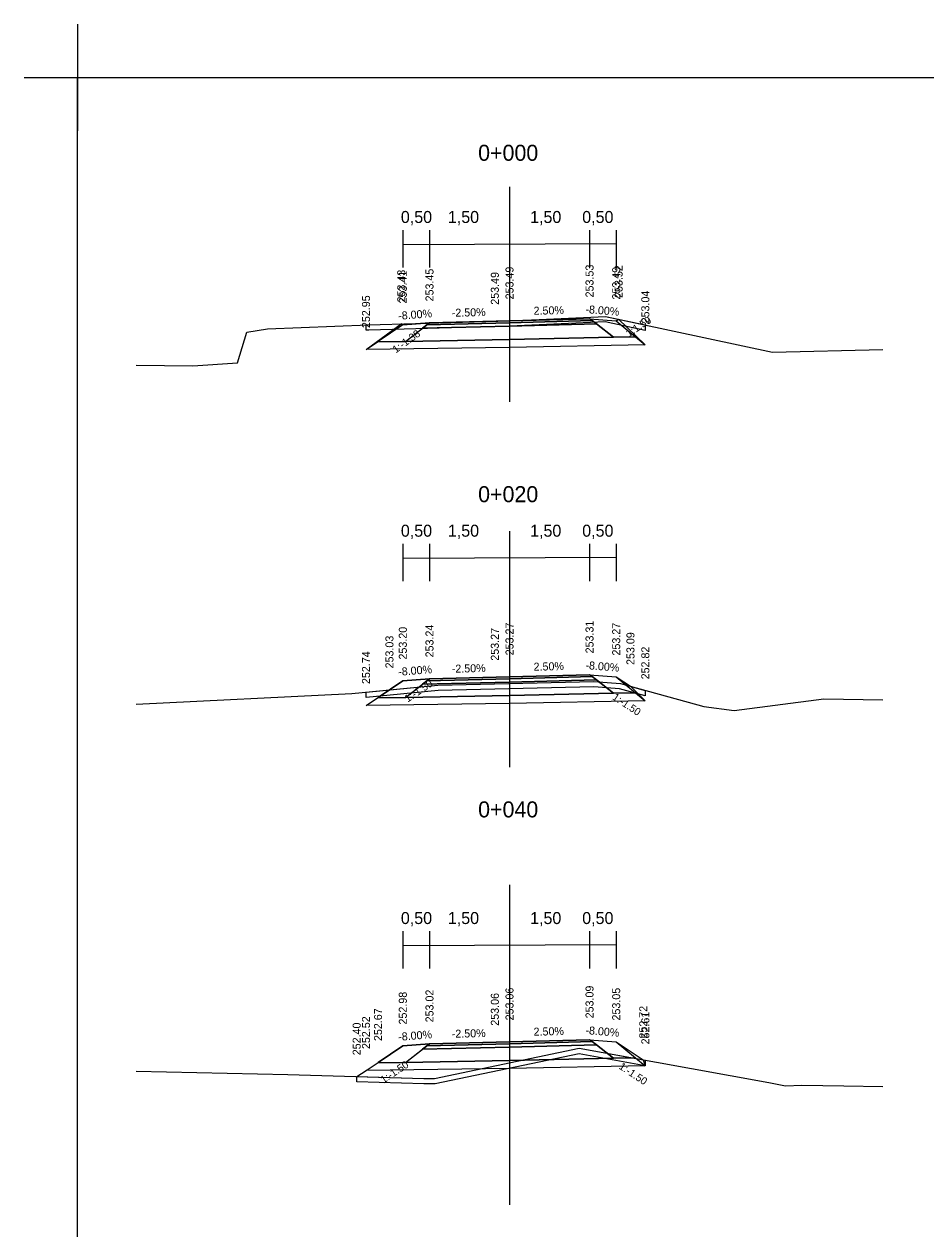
# Model space of a CAD drawing. Extents: x -552501 to -552394, y -1029983 to -1029892.
# Drawn here: x -552500.76 to -552483.85, y -1029914.93 to -1029892.35 of the extents above; entities that cross this region are included whole.
import ezdxf

# ---------------------------------------------------------------- set-up
doc = ezdxf.new("R2010")
doc.units = 0
for name, color, linetype in [('1', 7, 'Continuous'), ('16', 7, 'Continuous'), ('60', 7, 'Continuous'), ('9', 7, 'Continuous'), ('FORMATY', 7, 'Continuous'), ('Implicitní', 7, 'Continuous'), ('rámeček', 7, 'Continuous')]:
    doc.layers.add(name, color=color, linetype=linetype)

msp = doc.modelspace()

# ---------------------------------------------------------------- linework, layer by layer
for points in [[(-552498.656, -1029898.742), (-552497.595, -1029898.754), (-552496.757, -1029898.699), (-552496.581, -1029898.126), (-552496.19, -1029898.065), (-552494.3, -1029897.986), (-552491.655, -1029897.91), (-552489.854, -1029897.831), (-552486.728, -1029898.499), (-552484.656, -1029898.452)], [(-552494.346, -1029898.448), (-552493.685, -1029897.968), (-552493.656, -1029897.988), (-552493.156, -1029897.948), (-552491.656, -1029897.91), (-552490.156, -1029897.873), (-552489.656, -1029897.913), (-552489.611, -1029897.883), (-552489.11, -1029898.36)], [(-552493.656, -1029897.988), (-552493.685, -1029897.968)], [(-552494.346, -1029905.12), (-552493.907, -1029904.827), (-552493.656, -1029904.66), (-552493.156, -1029904.62), (-552491.656, -1029904.582), (-552490.156, -1029904.545), (-552489.656, -1029904.585), (-552489.389, -1029904.762), (-552489.11, -1029905.032)], [(-552498.656, -1029905.096), (-552494.612, -1029904.894), (-552492.998, -1029904.741), (-552490.075, -1029904.675), (-552489.575, -1029904.712), (-552488.014, -1029905.138), (-552487.443, -1029905.218), (-552485.762, -1029904.997), (-552484.656, -1029905.016)], [(-552494.521, -1029912.078), (-552494.346, -1029911.961), (-552494.121, -1029911.811), (-552493.656, -1029911.501), (-552493.156, -1029911.461), (-552491.656, -1029911.424), (-552490.156, -1029911.386), (-552489.656, -1029911.426), (-552489.148, -1029911.765), (-552489.11, -1029911.874)], [(-552498.656, -1029911.977), (-552495.809, -1029912.041), (-552493.261, -1029912.115), (-552493.059, -1029912.115), (-552490.352, -1029911.547), (-552486.792, -1029912.191), (-552486.485, -1029912.25), (-552486.178, -1029912.236), (-552485.386, -1029912.249), (-552484.656, -1029912.263)]]:
    msp.add_lwpolyline(points)
for points in [[(-552494.346, -1029897.988), (-552494.3, -1029897.986), (-552491.655, -1029897.91), (-552489.854, -1029897.831), (-552489.11, -1029897.99), (-552489.11, -1029898.092), (-552489.863, -1029897.931), (-552491.651, -1029898.01), (-552494.296, -1029898.086), (-552494.346, -1029898.088)], [(-552491.656, -1029897.95), (-552493.207, -1029897.988), (-552493.284, -1029898.048), (-552491.656, -1029898.01), (-552490.028, -1029897.967), (-552490.105, -1029897.907), (-552491.656, -1029897.95), (-552490.105, -1029897.907), (-552490.156, -1029897.873), (-552491.656, -1029897.91), (-552493.156, -1029897.948), (-552493.207, -1029897.988)], [(-552490.156, -1029897.873), (-552489.656, -1029897.913), (-552489.295, -1029898.21), (-552489.706, -1029898.217), (-552490.028, -1029897.967), (-552490.105, -1029897.907)], [(-552493.156, -1029897.948), (-552493.656, -1029897.988), (-552494.121, -1029898.298), (-552493.606, -1029898.298)], [(-552493.606, -1029898.298), (-552493.284, -1029898.048), (-552491.656, -1029898.01), (-552490.028, -1029897.967), (-552489.706, -1029898.217), (-552491.656, -1029898.26)], [(-552493.284, -1029898.048), (-552493.207, -1029897.988), (-552491.656, -1029897.95), (-552490.105, -1029897.907), (-552490.028, -1029897.967), (-552491.656, -1029898.01)], [(-552494.346, -1029898.448), (-552494.121, -1029898.298), (-552493.606, -1029898.298), (-552491.656, -1029898.26), (-552489.706, -1029898.217), (-552489.295, -1029898.21), (-552489.11, -1029898.36), (-552491.656, -1029898.41)], [(-552493.156, -1029904.62), (-552493.656, -1029904.66), (-552494.121, -1029904.97), (-552493.606, -1029904.97)], [(-552493.606, -1029904.97), (-552493.284, -1029904.72), (-552491.656, -1029904.682), (-552490.028, -1029904.639), (-552489.706, -1029904.889), (-552491.656, -1029904.932)], [(-552491.656, -1029904.622), (-552493.207, -1029904.66), (-552493.284, -1029904.72), (-552491.656, -1029904.682), (-552490.028, -1029904.639), (-552490.105, -1029904.579), (-552491.656, -1029904.622), (-552490.105, -1029904.579), (-552490.156, -1029904.545), (-552491.656, -1029904.582), (-552493.156, -1029904.62), (-552493.207, -1029904.66)], [(-552493.284, -1029904.72), (-552493.207, -1029904.66), (-552491.656, -1029904.622), (-552490.105, -1029904.579), (-552490.028, -1029904.639), (-552491.656, -1029904.682)], [(-552490.156, -1029904.545), (-552489.656, -1029904.585), (-552489.295, -1029904.882), (-552489.706, -1029904.889), (-552490.028, -1029904.639), (-552490.105, -1029904.579)], [(-552494.346, -1029904.869), (-552492.998, -1029904.741), (-552490.075, -1029904.675), (-552489.575, -1029904.712), (-552489.11, -1029904.839), (-552489.11, -1029904.942), (-552489.592, -1029904.811), (-552490.078, -1029904.775), (-552492.992, -1029904.841), (-552494.346, -1029904.969)], [(-552494.346, -1029905.12), (-552494.121, -1029904.97), (-552493.606, -1029904.97), (-552491.656, -1029904.932), (-552489.706, -1029904.889), (-552489.295, -1029904.882), (-552489.11, -1029905.032), (-552491.656, -1029905.082)], [(-552491.656, -1029911.464), (-552493.207, -1029911.501), (-552493.284, -1029911.561), (-552491.656, -1029911.524), (-552490.028, -1029911.48), (-552490.105, -1029911.42), (-552491.656, -1029911.464), (-552490.105, -1029911.42), (-552490.156, -1029911.386), (-552491.656, -1029911.424), (-552493.156, -1029911.461), (-552493.207, -1029911.501)], [(-552493.284, -1029911.561), (-552493.207, -1029911.501), (-552491.656, -1029911.464), (-552490.105, -1029911.42), (-552490.028, -1029911.48), (-552491.656, -1029911.524)], [(-552490.156, -1029911.386), (-552489.656, -1029911.426), (-552489.295, -1029911.724), (-552489.706, -1029911.73), (-552490.028, -1029911.48), (-552490.105, -1029911.42)], [(-552494.521, -1029912.078), (-552493.261, -1029912.115), (-552493.059, -1029912.115), (-552490.352, -1029911.547), (-552489.11, -1029911.772), (-552489.11, -1029911.873), (-552490.351, -1029911.649), (-552493.049, -1029912.215), (-552493.263, -1029912.215), (-552494.521, -1029912.178)], [(-552493.156, -1029911.461), (-552493.656, -1029911.501), (-552494.121, -1029911.811), (-552493.606, -1029911.811)], [(-552493.606, -1029911.811), (-552493.284, -1029911.561), (-552491.656, -1029911.524), (-552490.028, -1029911.48), (-552489.706, -1029911.73), (-552491.656, -1029911.774)], [(-552494.346, -1029911.961), (-552494.121, -1029911.811), (-552493.606, -1029911.811), (-552491.656, -1029911.774), (-552489.706, -1029911.73), (-552489.295, -1029911.724), (-552489.11, -1029911.874), (-552491.656, -1029911.924)]]:
    msp.add_lwpolyline(points, close=True)
at = {"layer": '60'}
for p, q in [((-552491.656, -1029895.399), (-552491.656, -1029899.431)), ((-552491.656, -1029901.855), (-552491.656, -1029906.279)), ((-552491.656, -1029908.481), (-552491.656, -1029914.481))]:
    msp.add_line(p, q, dxfattribs=at)
at = {"layer": '9'}
for p, q in [((-552493.656, -1029896.213), (-552493.656, -1029896.91)), ((-552493.156, -1029896.213), (-552493.156, -1029896.91)), ((-552491.656, -1029896.213), (-552491.656, -1029897.713)), ((-552490.156, -1029896.213), (-552490.156, -1029896.91)), ((-552489.656, -1029896.213), (-552489.656, -1029896.91)), ((-552493.656, -1029902.093), (-552493.656, -1029902.791)), ((-552493.156, -1029902.093), (-552493.156, -1029902.791)), ((-552491.656, -1029902.093), (-552491.656, -1029903.593)), ((-552490.156, -1029902.093), (-552490.156, -1029902.791)), ((-552489.656, -1029902.093), (-552489.656, -1029902.791)), ((-552493.656, -1029909.353), (-552493.656, -1029910.051)), ((-552493.156, -1029909.353), (-552493.156, -1029910.051)), ((-552491.656, -1029909.353), (-552491.656, -1029910.853)), ((-552490.156, -1029909.353), (-552490.156, -1029910.051)), ((-552489.656, -1029909.353), (-552489.656, -1029910.051))]:
    msp.add_line(p, q, dxfattribs=at)
at = {"layer": 'FORMATY'}
for p, q in [((-552499.755, -1029892.35), (-552499.755, -1029894.35)), ((-552500.755, -1029893.35), (-552498.755, -1029893.35))]:
    msp.add_line(p, q, dxfattribs=at)
at = {"layer": 'Implicitní'}
for p, q in [((-552493.646, -1029896.48), (-552489.656, -1029896.463)), ((-552493.646, -1029902.361), (-552489.656, -1029902.343)), ((-552493.646, -1029909.62), (-552489.656, -1029909.603))]:
    msp.add_line(p, q, dxfattribs=at)
at = {"layer": 'rámeček'}
for p, q in [((-552499.755, -1029893.35), (-552394.755, -1029893.35)), ((-552499.755, -1029923.05), (-552499.755, -1029893.35))]:
    msp.add_line(p, q, dxfattribs=at)

# ---------------------------------------------------------------- texts
for s, rotation, p in [('1:1.50', 33.6902, (-552489.417, -1029898.222)), ('1:-1.38', 35.9449, (-552493.786, -1029898.524)), ('1:-1.50', 33.6902, (-552493.565, -1029905.068)), ('1:-1.50', 326.3098, (-552489.739, -1029904.998)), ('1:-1.50', 33.6905, (-552494.017, -1029912.211)), ('1:-1.50', 326.3098, (-552489.618, -1029911.92))]:
    msp.add_text(s, height=0.14, rotation=rotation).set_placement(p)
at = {"layer": '1'}
for s, p in [('0+000', (-552492.244, -1029894.912)), ('0+020', (-552492.244, -1029901.311)), ('0+040', (-552492.244, -1029907.219))]:
    msp.add_text(s, height=0.3, dxfattribs=at).set_placement(p)
at = {"layer": '16'}
for s, p in [('0,50', (-552493.693, -1029896.078)), ('1,50', (-552492.812, -1029896.078)), ('1,50', (-552491.27, -1029896.078)), ('0,50', (-552490.293, -1029896.078)), ('0,50', (-552493.693, -1029901.958)), ('1,50', (-552492.812, -1029901.958)), ('1,50', (-552491.27, -1029901.958)), ('0,50', (-552490.293, -1029901.958)), ('0,50', (-552493.693, -1029909.218)), ('1,50', (-552492.812, -1029909.218)), ('1,50', (-552491.27, -1029909.218)), ('0,50', (-552490.293, -1029909.218))]:
    msp.add_text(s, height=0.225, dxfattribs=at).set_placement(p)
for s, rotation, p in [('253.43', 90, (-552493.61, -1029897.568)), ('253.45', 90, (-552493.081, -1029897.548)), ('253.49', 90, (-552491.581, -1029897.51)), ('253.53', 90, (-552490.081, -1029897.473)), ('253.49', 90, (-552489.581, -1029897.513)), ('253.52', 90, (-552489.536, -1029897.483)), ('253.41', 90, (-552493.581, -1029897.588)), ('253.49', 90, (-552491.856, -1029897.61)), ('253.04', 90, (-552489.035, -1029897.96)), ('252.95', 90, (-552494.271, -1029898.048)), ('2.50%', 1.4321, (-552491.203, -1029897.799)), ('-8.00%', 355.4261, (-552490.237, -1029897.766)), ('-8.00%', 4.5739, (-552493.737, -1029897.894)), ('-2.50%', 1.4321, (-552492.737, -1029897.837)), ('253.20', 90, (-552493.581, -1029904.26)), ('253.24', 90, (-552493.081, -1029904.22)), ('253.27', 90, (-552491.856, -1029904.282)), ('253.27', 90, (-552491.581, -1029904.182)), ('253.31', 90, (-552490.081, -1029904.145)), ('253.27', 90, (-552489.581, -1029904.185)), ('253.03', 90, (-552493.832, -1029904.427)), ('253.09', 90, (-552489.314, -1029904.362)), ('252.74', 90, (-552494.271, -1029904.72)), ('252.82', 90, (-552489.035, -1029904.632)), ('-8.00%', 4.5739, (-552493.737, -1029904.566)), ('-2.50%', 1.4321, (-552492.737, -1029904.509)), ('2.50%', 1.4321, (-552491.203, -1029904.471)), ('-8.00%', 355.4261, (-552490.237, -1029904.438)), ('252.98', 90, (-552493.581, -1029911.101)), ('253.02', 90, (-552493.081, -1029911.061)), ('253.06', 90, (-552491.856, -1029911.124)), ('253.06', 90, (-552491.581, -1029911.024)), ('253.09', 90, (-552490.081, -1029910.986)), ('253.05', 90, (-552489.581, -1029911.026)), ('252.52', 90, (-552494.271, -1029911.561)), ('252.67', 90, (-552494.046, -1029911.411)), ('252.72', 90, (-552489.073, -1029911.365)), ('252.61', 90, (-552489.035, -1029911.474)), ('252.40', 90, (-552494.446, -1029911.678)), ('-2.50%', 1.4321, (-552492.737, -1029911.351)), ('2.50%', 1.4321, (-552491.203, -1029911.312)), ('-8.00%', 355.4261, (-552490.237, -1029911.28)), ('-8.00%', 4.5739, (-552493.737, -1029911.408))]:
    msp.add_text(s, height=0.15, rotation=rotation, dxfattribs=at).set_placement(p)

doc.saveas('drawing.dxf')
